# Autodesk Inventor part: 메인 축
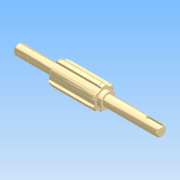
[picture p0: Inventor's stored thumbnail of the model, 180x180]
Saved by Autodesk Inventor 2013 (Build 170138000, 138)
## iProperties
Created: 2012-05
Part Number: 메인 축
Document SubType Name: 모델링
Designer: SeoGD™
Mass: 168.566 g
Surface Area: 72.5108 cm^2
Volume: 21.4461 cm^3
Density: 7.86 g/cm^3
Material: 강철, 연강
변환 표준: STEP AP214IS
파일 이름: C:\Users\SeoGD\Desktop\?쒗뿕\硫붿씤 異?.stp
전처리기: Build: 253, Release: 2010 SP1 - Date: Wed 07/29/2009
전송 단위: 밀리미터
불확실성: 0.01
Author: SeoGD™
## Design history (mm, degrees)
sketch "스케치1"
  geometry: L1 (-69.5, 0)-(69.5, 0); L2 (69.5, 0)-(69.5, 5); L3 (69.5, 5)-(55.5, 5); L4 (55.5, 5)-(55.5, 4.8); L5 (55.5, 4.8)-(54.35, 4.8); L6 (54.35, 4.8)-(54.35, 5); L7 (54.35, 5)-(30.5, 5); L8 (30.5, 5)-(30.5, 9); L9 (30.5, 9)-(-13.5, 9); L10 (-13.5, 9)-(-13.5, 7); L11 (-13.5, 7)-(-17.5, 7); L12 (-17.5, 7)-(-17.5, 5); L13 (-17.5, 5)-(-69.5, 5); L14 (-69.5, 5)-(-69.5, 0); 2 further points
  constraints: 28 end point, 9 parallel, 4 collinear, 2 perpendicular, 1 coincident, 1 horizontal, 1 midpoint
  dimensions: "d2" = 1.15 distance between parallel lines of L6 L4; "d3" = 10 diameter of L3 L1; "d4" = 9.6 diameter of L5 L1; "d6" = 44 distance between parallel lines of L10 L8; "d7" = 4 distance between parallel lines of L12 L10; "d8" = 14 diameter of L11 L1; "d9" = 18 diameter of L9 L1; "d33" = 52 distance from line of L12.end L14; "d37" = 39 distance between parallel lines of L8 L2; "d38" = 14 distance between parallel lines of L2 L4
revolve "회전1" sketch "스케치1" stored, may be unused: angle "d10" = 90 deg
sketch "스케치2"
  geometry: L1 (2.5, 10.712)-(2.5, 8.646); L2 (-2.5, 10.712)-(-2.5, 8.646); A1 r 9 centre (0, 0) between (2.5, 8.646) and (-2.5, 8.646) reference; A2 r 11 centre (0, 0) between (2.5, 10.712) and (-2.5, 10.712); 1 further point
  constraints: 4 end point, 4 point on circle, 2 parallel, 1 centre point, 1 coincident, 1 vertical
  dimensions: "d11" = 22 diameter of A2; "d12" = 5 distance between parallel lines of L1 L2
extrude "돌출1" join sketch "스케치2" stored distance "d13" = 10; taper "d14" = 0 deg
chamfer "모따기1" distance "d15" = 1; stored, may be unused: second distance "d16" = 2, angle "d17" = 45 deg
node "작업 평면1"
node "작업 평면2"
sketch "스케치3"
  geometry: L1 (2.5, 10.712)-(2.5, 10.198); L2 (-2.5, 10.712)-(-2.5, 10.198); A1 r 11 centre (0, 0) between (2.5, 10.712) and (-2.5, 10.712) reference; A2 r 10.5 centre (0, 0) between (2.5, 10.198) and (-2.5, 10.198); 1 further point
  constraints: 4 end point, 2 point on circle, 1 centre point, 1 coincident, 1 parallel, 1 vertical
  dimensions: "d19" = 21 diameter of A2
extrude "돌출2" cut sketch "스케치3" distance "d20" = 1.35; taper "d21" = 0 deg
node "작업 평면3"
sketch "스케치4"
  geometry: L1 (-26, -5)-(-26, 5) reference; L2 (-26, 1.5)-(-12.5, 1.5); L3 (-12.5, -1.5)-(-26, -1.5); A1 r 1.5 centre (-12.5, 0) between (-12.5, -1.5) and (-12.5, 1.5); 2 further points
  constraints: 4 end point, 2 perpendicular, 2 point on circle, 2 point on line, 2 tangent, 1 centre point, 1 horizontal alignment, 1 midpoint
  dimensions: "d25" = 3 distance between parallel lines of L3 L2; "d26" = 15 dimension on A1 L1
extrude "돌출3" cut sketch "스케치4" distance "d27" = 1.8; taper "d28" = 0 deg
chamfer "모따기2" distance "d29" = 1; stored, may be unused: second distance "d30" = 2, angle "d31" = 45 deg
node "솔리드1"
node "솔리드 본체"
node "곡면 본체"
mirror "대칭1"
pattern_circular "원형 패턴1" dims "d23" = 360 deg
node "솔리드2"
other parameters: "d18" = -1.65
